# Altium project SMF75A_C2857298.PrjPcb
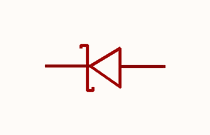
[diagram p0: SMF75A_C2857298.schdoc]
1 sheet, 1 parts. Net scope: global (net labels, ports and power ports of the same name join across sheets).

## Sheet SMF75A_C2857298.schdoc
size 127 x 101 mm

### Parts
D?  smf75a_c2857298  [SOD-123FL_L2.8-W1.8-LS3.6-RD]  (value not drawn)

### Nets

Not connected (* = marked no-connect by the designer): D? 1(K) 2(A)

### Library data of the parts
D? = smf75a_c2857298: 极性:单向;反向截止电压(Vrwm):75V;钳位电压:121V;峰值脉冲电流(Ipp):1.7A;峰值脉冲功率(Ppp):200W@10/1000us;击穿电压(VBR):83.3V;; Manufacturer: JSMSEMI(杰盛微); ManufacturerPart: SMF75A; AddInBom: yes; ModelId: 9a6bf0a398604d2998ad78800a7c8ef9; ModelTransform: 141.732,70.866,0,0,0,0,0,0,0; Polarity: 单向; Reverse Stand-Off Voltage (Vrwm): 75V; Clamping Voltage: 121V; Peak Pulse Current (Ipp): 1.7A; Voltage - Breakdown: 83.3V; Reverse Leakage Current (Ir): 1uA; Number of Channels: 单路; Type: TVS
